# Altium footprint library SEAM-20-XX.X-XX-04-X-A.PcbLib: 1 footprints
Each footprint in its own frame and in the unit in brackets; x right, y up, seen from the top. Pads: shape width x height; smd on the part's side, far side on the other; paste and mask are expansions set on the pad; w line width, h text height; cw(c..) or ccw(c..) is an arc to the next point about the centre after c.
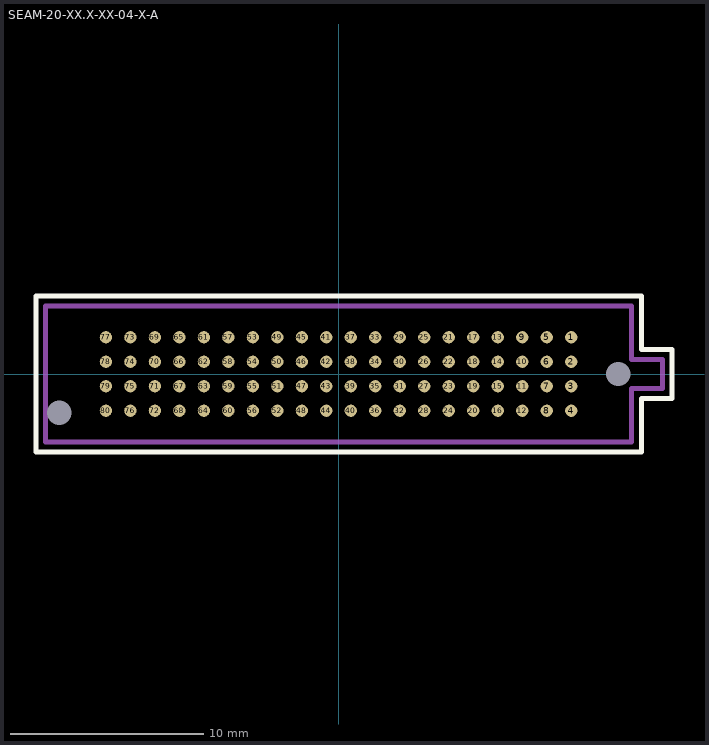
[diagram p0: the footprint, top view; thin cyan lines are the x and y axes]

## SEAM-20-XX.X-XX-04-X-A [mil]
pads (82):
  round 25 smd paste+5 mask+2: 1(475,75) 2(475,25) 3(475,-25) 4(475,-75) 5(425,75) 6(425,25) 7(425,-25) 8(425,-75) 9(375,75) 10(375,25) 11(375,-25) 12(375,-75) 13(325,75) 14(325,25) 15(325,-25) 16(325,-75) 17(275,75) 18(275,25) 19(275,-25) 20(275,-75) 21(225,75) 22(225,25) 23(225,-25) 24(225,-75) 25(175,75) 26(175,25) 27(175,-25) 28(175,-75) 29(125,75) 30(125,25) 31(125,-25) 32(125,-75) 33(75,75) 34(75,25) 35(75,-25) 36(75,-75) 37(25,75) 38(25,25) 39(25,-25) 40(25,-75) 41(-25,75) 42(-25,25) 43(-25,-25) 44(-25,-75) 45(-75,75) 46(-75,25) 47(-75,-25) 48(-75,-75) 49(-125,75) 50(-125,25) 51(-125,-25) 52(-125,-75) 53(-175,75) 54(-175,25) 55(-175,-25) 56(-175,-75) 57(-225,75) 58(-225,25) 59(-225,-25) 60(-225,-75) 61(-275,75) 62(-275,25) 63(-275,-25) 64(-275,-75) 65(-325,75) 66(-325,25) 67(-325,-25) 68(-325,-75) 69(-375,75) 70(-375,25) 71(-375,-25) 72(-375,-75) 73(-425,75) 74(-425,25) 75(-425,-25) 76(-425,-75) 77(-475,75) 78(-475,25) 79(-475,-25) 80(-475,-75)
  round 0 hole 50 unplated: 81(570.5,0) 82(-570.5,-79)
Top Overlay:
  lines w10: -618,-159 618,-159 618,-50 681,-50 681,50 618,50 618,159 -618,159 -618,-159
Mechanical 1:
  lines w10: -598,-139 598,-139 598,-30 661,-30 661,30 598,30 598,139 -598,139 -598,-139
  text "J1" at -17.57,-18 h30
